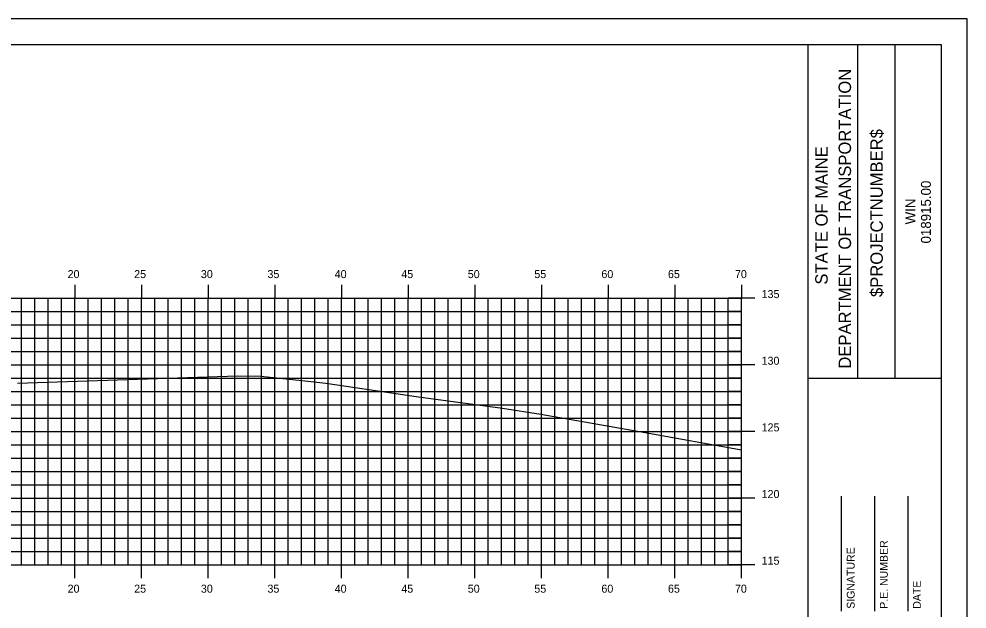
# Model space of a CAD drawing. Extents: x 851295 to 851467, y 365624 to 365734.
# Drawn here: x 851393.8 to 851464.9, y 365689.7 to 365734 of the extents above; entities that cross this region are included whole.
import ezdxf

# ---------------------------------------------------------------- set-up
doc = ezdxf.new("R2010")
doc.units = 0
for name, color, linetype in [('BORDER', 7, 'Continuous'), ('H_V ANNOTATION', 7, 'Continuous'), ('MAJOR', 7, 'Continuous'), ('MINOR', 7, 'Continuous'), ('PLOT BOUNDARY', 7, 'Continuous'), ('S_Roadway_Centerline', 7, 'Continuous')]:
    doc.layers.add(name, color=color, linetype=linetype)

msp = doc.modelspace()

# ---------------------------------------------------------------- linework, layer by layer
at = {"layer": 'BORDER'}
for p, q in [((851453.009, 365627.027), (851453.009, 365732.027)), ((851456.738, 365707.024), (851456.738, 365732.024)), ((851459.533, 365707.024), (851459.533, 365732.024)), ((851453.01, 365707.021), (851463.009, 365707.021)), ((851455.509, 365689.53), (851455.509, 365698.177)), ((851458.009, 365689.53), (851458.009, 365698.177)), ((851460.509, 365689.53), (851460.509, 365698.177))]:
    msp.add_line(p, q, dxfattribs=at)
msp.add_lwpolyline([(851303.009, 365627.027), (851463.009, 365627.027), (851463.009, 365732.027), (851303.009, 365732.027)], close=True, dxfattribs=at)
at = {"layer": 'MAJOR'}
for p, q in [((851398.009, 365714.029), (851398.009, 365713.027)), ((851403.009, 365714.029), (851403.009, 365713.027)), ((851408.009, 365714.029), (851408.009, 365713.027)), ((851413.009, 365714.029), (851413.009, 365713.027)), ((851418.009, 365714.029), (851418.009, 365713.027)), ((851423.009, 365714.029), (851423.009, 365713.027)), ((851428.009, 365714.029), (851428.009, 365713.027)), ((851433.009, 365714.029), (851433.009, 365713.027)), ((851438.009, 365714.029), (851438.009, 365713.027)), ((851443.009, 365714.029), (851443.009, 365713.027)), ((851448.009, 365714.029), (851448.009, 365713.027)), ((851308.009, 365713.027), (851448.009, 365713.027)), ((851308.009, 365713.027), (851448.009, 365713.027)), ((851398.009, 365693.027), (851398.009, 365713.027)), ((851403.009, 365693.027), (851403.009, 365713.027)), ((851408.009, 365693.027), (851408.009, 365713.027)), ((851413.009, 365693.027), (851413.009, 365713.027)), ((851418.009, 365693.027), (851418.009, 365713.027)), ((851423.009, 365693.027), (851423.009, 365713.027)), ((851428.009, 365693.027), (851428.009, 365713.027)), ((851433.009, 365693.027), (851433.009, 365713.027)), ((851438.009, 365693.027), (851438.009, 365713.027)), ((851443.009, 365693.027), (851443.009, 365713.027)), ((851449.011, 365713.027), (851447.007, 365713.027)), ((851448.009, 365693.027), (851448.009, 365713.027)), ((851448.009, 365693.027), (851448.009, 365713.027)), ((851308.009, 365708.027), (851448.009, 365708.027)), ((851449.011, 365708.027), (851447.007, 365708.027)), ((851308.009, 365703.027), (851448.009, 365703.027)), ((851449.011, 365703.027), (851447.007, 365703.027)), ((851308.009, 365698.027), (851448.009, 365698.027)), ((851449.011, 365698.027), (851447.007, 365698.027)), ((851308.009, 365693.027), (851448.009, 365693.027)), ((851308.009, 365693.027), (851448.009, 365693.027)), ((851398.009, 365692.025), (851398.009, 365693.027)), ((851403.009, 365692.025), (851403.009, 365693.027)), ((851408.009, 365692.025), (851408.009, 365693.027)), ((851413.009, 365692.025), (851413.009, 365693.027)), ((851418.009, 365692.025), (851418.009, 365693.027)), ((851423.009, 365692.025), (851423.009, 365693.027)), ((851428.009, 365692.025), (851428.009, 365693.027)), ((851433.009, 365692.025), (851433.009, 365693.027)), ((851438.009, 365692.025), (851438.009, 365693.027)), ((851443.009, 365692.025), (851443.009, 365693.027)), ((851449.011, 365693.027), (851447.007, 365693.027)), ((851448.009, 365692.025), (851448.009, 365693.027))]:
    msp.add_line(p, q, dxfattribs=at)
at = {"layer": 'MINOR'}
for p, q in [((851394.009, 365693.027), (851394.009, 365713.027)), ((851395.009, 365693.027), (851395.009, 365713.027)), ((851396.009, 365693.027), (851396.009, 365713.027)), ((851397.009, 365693.027), (851397.009, 365713.027)), ((851399.009, 365693.027), (851399.009, 365713.027)), ((851400.009, 365693.027), (851400.009, 365713.027)), ((851401.009, 365693.027), (851401.009, 365713.027)), ((851402.009, 365693.027), (851402.009, 365713.027)), ((851404.009, 365693.027), (851404.009, 365713.027)), ((851405.009, 365693.027), (851405.009, 365713.027)), ((851406.009, 365693.027), (851406.009, 365713.027)), ((851407.009, 365693.027), (851407.009, 365713.027)), ((851409.009, 365693.027), (851409.009, 365713.027)), ((851410.009, 365693.027), (851410.009, 365713.027)), ((851411.009, 365693.027), (851411.009, 365713.027)), ((851412.009, 365693.027), (851412.009, 365713.027)), ((851414.009, 365693.027), (851414.009, 365713.027)), ((851415.009, 365693.027), (851415.009, 365713.027)), ((851416.009, 365693.027), (851416.009, 365713.027)), ((851417.009, 365693.027), (851417.009, 365713.027)), ((851419.009, 365693.027), (851419.009, 365713.027)), ((851420.009, 365693.027), (851420.009, 365713.027)), ((851421.009, 365693.027), (851421.009, 365713.027)), ((851422.009, 365693.027), (851422.009, 365713.027)), ((851424.009, 365693.027), (851424.009, 365713.027)), ((851425.009, 365693.027), (851425.009, 365713.027)), ((851426.009, 365693.027), (851426.009, 365713.027)), ((851427.009, 365693.027), (851427.009, 365713.027)), ((851429.009, 365693.027), (851429.009, 365713.027)), ((851430.009, 365693.027), (851430.009, 365713.027)), ((851431.009, 365693.027), (851431.009, 365713.027)), ((851432.009, 365693.027), (851432.009, 365713.027)), ((851434.009, 365693.027), (851434.009, 365713.027)), ((851435.009, 365693.027), (851435.009, 365713.027)), ((851436.009, 365693.027), (851436.009, 365713.027)), ((851437.009, 365693.027), (851437.009, 365713.027)), ((851439.009, 365693.027), (851439.009, 365713.027)), ((851440.009, 365693.027), (851440.009, 365713.027)), ((851441.009, 365693.027), (851441.009, 365713.027)), ((851442.009, 365693.027), (851442.009, 365713.027)), ((851444.009, 365693.027), (851444.009, 365713.027)), ((851445.009, 365693.027), (851445.009, 365713.027)), ((851446.009, 365693.027), (851446.009, 365713.027)), ((851447.009, 365693.027), (851447.009, 365713.027)), ((851308.009, 365712.027), (851448.009, 365712.027)), ((851448.009, 365712.027), (851447.007, 365712.027)), ((851308.009, 365711.027), (851448.009, 365711.027)), ((851448.009, 365711.027), (851447.007, 365711.027)), ((851308.009, 365710.027), (851448.009, 365710.027)), ((851448.009, 365710.027), (851447.007, 365710.027)), ((851308.009, 365709.027), (851448.009, 365709.027)), ((851448.009, 365709.027), (851447.007, 365709.027)), ((851308.009, 365707.027), (851448.009, 365707.027)), ((851448.009, 365707.027), (851447.007, 365707.027)), ((851308.009, 365706.027), (851448.009, 365706.027)), ((851448.009, 365706.027), (851447.007, 365706.027)), ((851308.009, 365705.027), (851448.009, 365705.027)), ((851448.009, 365705.027), (851447.007, 365705.027)), ((851308.009, 365704.027), (851448.009, 365704.027)), ((851448.009, 365704.027), (851447.007, 365704.027)), ((851308.009, 365702.027), (851448.009, 365702.027)), ((851448.009, 365702.027), (851447.007, 365702.027)), ((851308.009, 365701.027), (851448.009, 365701.027)), ((851448.009, 365701.027), (851447.007, 365701.027)), ((851308.009, 365700.027), (851448.009, 365700.027)), ((851448.009, 365700.027), (851447.007, 365700.027)), ((851308.009, 365699.027), (851448.009, 365699.027)), ((851448.009, 365699.027), (851447.007, 365699.027)), ((851308.009, 365697.027), (851448.009, 365697.027)), ((851448.009, 365697.027), (851447.007, 365697.027)), ((851308.009, 365696.027), (851448.009, 365696.027)), ((851448.009, 365696.027), (851447.007, 365696.027)), ((851308.009, 365695.027), (851448.009, 365695.027)), ((851448.009, 365695.027), (851447.007, 365695.027)), ((851308.009, 365694.027), (851448.009, 365694.027)), ((851448.009, 365694.027), (851447.007, 365694.027))]:
    msp.add_line(p, q, dxfattribs=at)
at = {"layer": 'PLOT BOUNDARY'}
msp.add_lwpolyline([(851294.916, 365623.968), (851464.916, 365623.968), (851464.916, 365733.968), (851294.916, 365733.968)], close=True, dxfattribs=at)
at = {"layer": 'S_Roadway_Centerline'}
msp.add_lwpolyline([(851393.7, 365706.643), (851410.21, 365707.188), (851411.95, 365707.169), (851415.029, 365706.839), (851416.832, 365706.645), (851423.776, 365705.631), (851430.078, 365704.777), (851432.955, 365704.311), (851440.778, 365702.942), (851448.009, 365701.647)], dxfattribs=at)

# ---------------------------------------------------------------- texts
at = {"layer": 'BORDER'}
for s, height, p in [('DEPARTMENT OF TRANSPORTATION', 0.93176, (851456.216, 365707.733)), ('$PROJECTNUMBER$', 0.93176, (851458.601, 365713.106)), ('STATE OF MAINE', 0.93176, (851454.465, 365714.039)), ('018915.00', 0.7453, (851462.205, 365717.125)), ('WIN', 0.7453, (851461.046, 365718.557)), ('P.E. NUMBER', 0.59055, (851458.97, 365689.722)), ('SIGNATURE', 0.5906, (851456.49, 365689.722)), ('DATE', 0.5906, (851461.45, 365689.722))]:
    msp.add_text(s, height=height, rotation=90, dxfattribs=at).set_placement(p)
at = {"layer": 'H_V ANNOTATION'}
for s, p in [('20', (851397.463, 365714.527)), ('25', (851402.455, 365714.527)), ('30', (851407.458, 365714.527)), ('35', (851412.45, 365714.527)), ('40', (851417.495, 365714.527)), ('45', (851422.487, 365714.527)), ('50', (851427.474, 365714.527)), ('55', (851432.466, 365714.527)), ('60', (851437.495, 365714.527)), ('65', (851442.487, 365714.527)), ('70', (851447.511, 365714.527)), ('135', (851449.509, 365713.027)), ('130', (851449.509, 365708.027)), ('125', (851449.509, 365703.027)), ('120', (851449.509, 365698.027)), ('115', (851449.509, 365693.027)), ('20', (851397.463, 365690.927)), ('25', (851402.455, 365690.927)), ('30', (851407.458, 365690.927)), ('35', (851412.45, 365690.927)), ('40', (851417.495, 365690.927)), ('45', (851422.487, 365690.927)), ('50', (851427.474, 365690.927)), ('55', (851432.466, 365690.927)), ('60', (851437.495, 365690.927)), ('65', (851442.487, 365690.927)), ('70', (851447.511, 365690.927))]:
    msp.add_text(s, height=0.6, dxfattribs=at).set_placement(p)

doc.saveas('drawing.dxf')
